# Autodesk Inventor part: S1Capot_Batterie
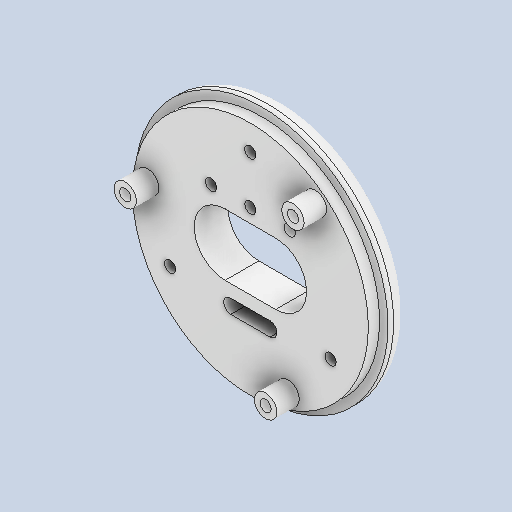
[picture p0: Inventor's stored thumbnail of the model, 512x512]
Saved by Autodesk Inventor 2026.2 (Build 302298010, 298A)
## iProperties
Created: 1601-01
Part Number: S1Capot_Batterie
Material: ABS
Document SubType Name: Modeling
Designer: mel
Density: 1.02 g/cm^3
Appearance: white-pw-mt11050
Author: mel
Sending System: SOLIDWORKS 2023
Part Number: Capot_Batterie
Last Saved Date: 2025-04-02
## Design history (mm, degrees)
feature "Congé1"
node "Solide1"
